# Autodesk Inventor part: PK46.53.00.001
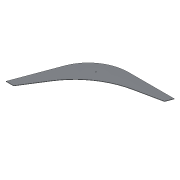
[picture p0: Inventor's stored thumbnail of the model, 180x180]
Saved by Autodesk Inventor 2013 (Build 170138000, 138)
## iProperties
Created: 2005-03
Part Number: PK46.53.00.001
Material: Steel, Mild
Document SubType Name: Modeling
Designer: HKostja
Manufacturer: Standard
Standards Organization: Custom
Density: 7.86 g/cm^3
Mass: 4881.47 g
Surface Area: 3207.19 cm^2
Volume: 621.052 cm^3
Author: HKostja
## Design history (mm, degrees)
sketch "Эскиз1"
  geometry: L1 (264.331, 0)-(690, 0); L2 (690, 0)-(665.652, -65.629); L3 (-170, -646.916)-(-240, -646.916); L4 (-240, -646.916)-(-91.941, -247.826); L5 (-170, -646.916)-(125.21, -180); L6 (665.652, -65.629)-(125.21, -180); L7 (0, 0)-(559.054, -803.691); L8 (-32.608, -429.61)-(-170, -646.916); L9 (414.127, -118.858)-(665.652, -65.629); C1 r 3.5 at (105, -150); A1 r 700 centre (559.054, -803.691) between (414.127, -118.858) and (-32.608, -429.61); A2 r 380 centre (264.331, -380) between (264.331, 0) and (-91.941, -247.826)
  constraints: 18 end point, 6 tangent, 5 point on line, 4 point on circle, 3 centre point, 2 collinear, 2 equal length, 2 parallel, 1 horizontal, 1 other
  dimensions: "d0" = 690 distance of L7.start L1.end; "d1" = 70 distance of L3.start L3.end; "d3" = 240 horizontal distance of L7.start L3.end; "d5" = 700 radius of A1; "d6" = 380 radius of A2; "d9" = 180 distance from line of L1 L5.end; "d11" = 7 diameter of C1; "d12" = 150 distance from line of L1 C1.centre; "d13" = 585 horizontal distance of L1.end C1.centre
extrude "Выдавливание1" new body sketch "Эскиз1" distance "d7" = 4; taper "d8" = 0 deg
body "Solid1"
